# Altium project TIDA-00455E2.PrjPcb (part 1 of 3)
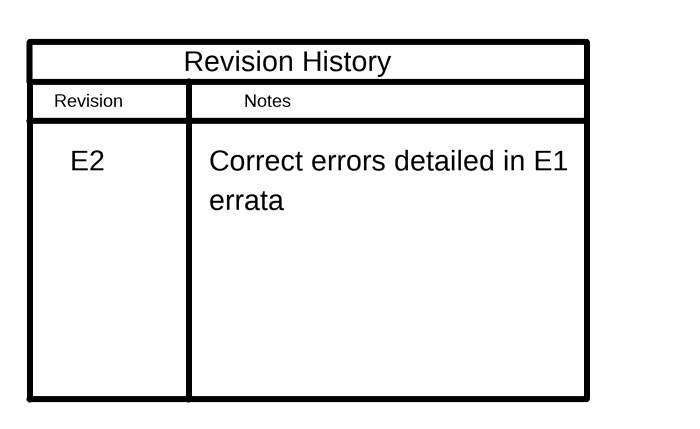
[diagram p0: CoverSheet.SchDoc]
TID: 00455; TechSupport: http://www.ti.com/support; SCH_Rev: E2.0; PRJ_Title: Four Channel Camera Board for TDA2x; PRJ_Number: TIDA-00455; PRJ_Engineer: Brian Shaffer; PRJ_Customer: Public Release; PCB_Rev: E2; EVM_Orderable: NO; CopyrightYear: 2015
10 sheets, 542 parts. Net scope: global (net labels, ports and power ports of the same name join across sheets).
Board file: TIDA-00455E2.PcbDoc
Sheets:
  CoverSheet.SchDoc
  cam_connections.SchDoc
  V_Batt_Supply.SchDoc
  Camera_Switch_and_Bucks.SchDoc
  Deserializer.SchDoc
  OV490_1.SchDoc
  OV490_2.SchDoc
  uC.SchDoc
  TDA2x_Conector.SchDoc
  Hardware.SchDoc

## Sheet CoverSheet.SchDoc: CoverSheet
size 431 x 279 mm; Date: Not shown in title block; ApprovedBy: Not shown in title block; CheckedBy: Not shown in title block; Author: Not shown in title block; CompanyName: Not shown in title block; DrawnBy: Brian Shaffer; Engineer: Not shown in title block; Organization: Not shown in title block; Address1: Not shown in title block; Address2: Not shown in title block; Address3: Not shown in title block; Address4: Not shown in title block; DocumentNumber: 1; Revision: Use project parameter SCH_Rev; SheetNumber: 1; SheetTotal: 10; PageSetup: Record=PageOptions¦CenterHorizontal=True¦CenterVertical=True¦PrintScale=1.00¦XCorrection=1.00¦YCorrection=1.00¦PrintKind=0¦BorderSize=5000000¦LeftOffset=0¦BottomOffset=0¦Orientation=2¦PaperLength=1000¦PaperWidth=1000¦Scale=100¦PaperSource=15¦PrintQuality=600¦MediaType=1¦DitherType=10¦PaperKind=Letter¦PrintScaleMode=1

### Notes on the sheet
- Revision
- Notes
- Revision History
- E2
- Correct errors detailed in E1
- errata

## Sheet cam_connections.SchDoc: cam_connections
size 431 x 279 mm; Date: Not shown in title block; ApprovedBy: Not shown in title block; CheckedBy: Not shown in title block; Author: Not shown in title block; CompanyName: Not shown in title block; DrawnBy: Brian Shaffer; Engineer: Not shown in title block; Organization: Not shown in title block; Address1: Not shown in title block; Address2: Not shown in title block; Address3: Not shown in title block; Address4: Not shown in title block; DocumentNumber: 2; Revision: Use project parameter SCH_Rev; SheetNumber: 2; SheetTotal: 10; PageSetup: Record=PageOptions¦CenterHorizontal=True¦CenterVertical=True¦PrintScale=0.64¦XCorrection=1.00¦YCorrection=1.00¦PrintKind=0¦BorderSize=5000000¦LeftOffset=0¦BottomOffset=0¦Orientation=2¦PaperLength=1000¦PaperWidth=1000¦Scale=100¦PaperSource=15¦PrintQuality=-3¦MediaType=1¦DitherType=10¦PrintScaleMode=1¦PaperKind=11x17¦PaperIndex=17
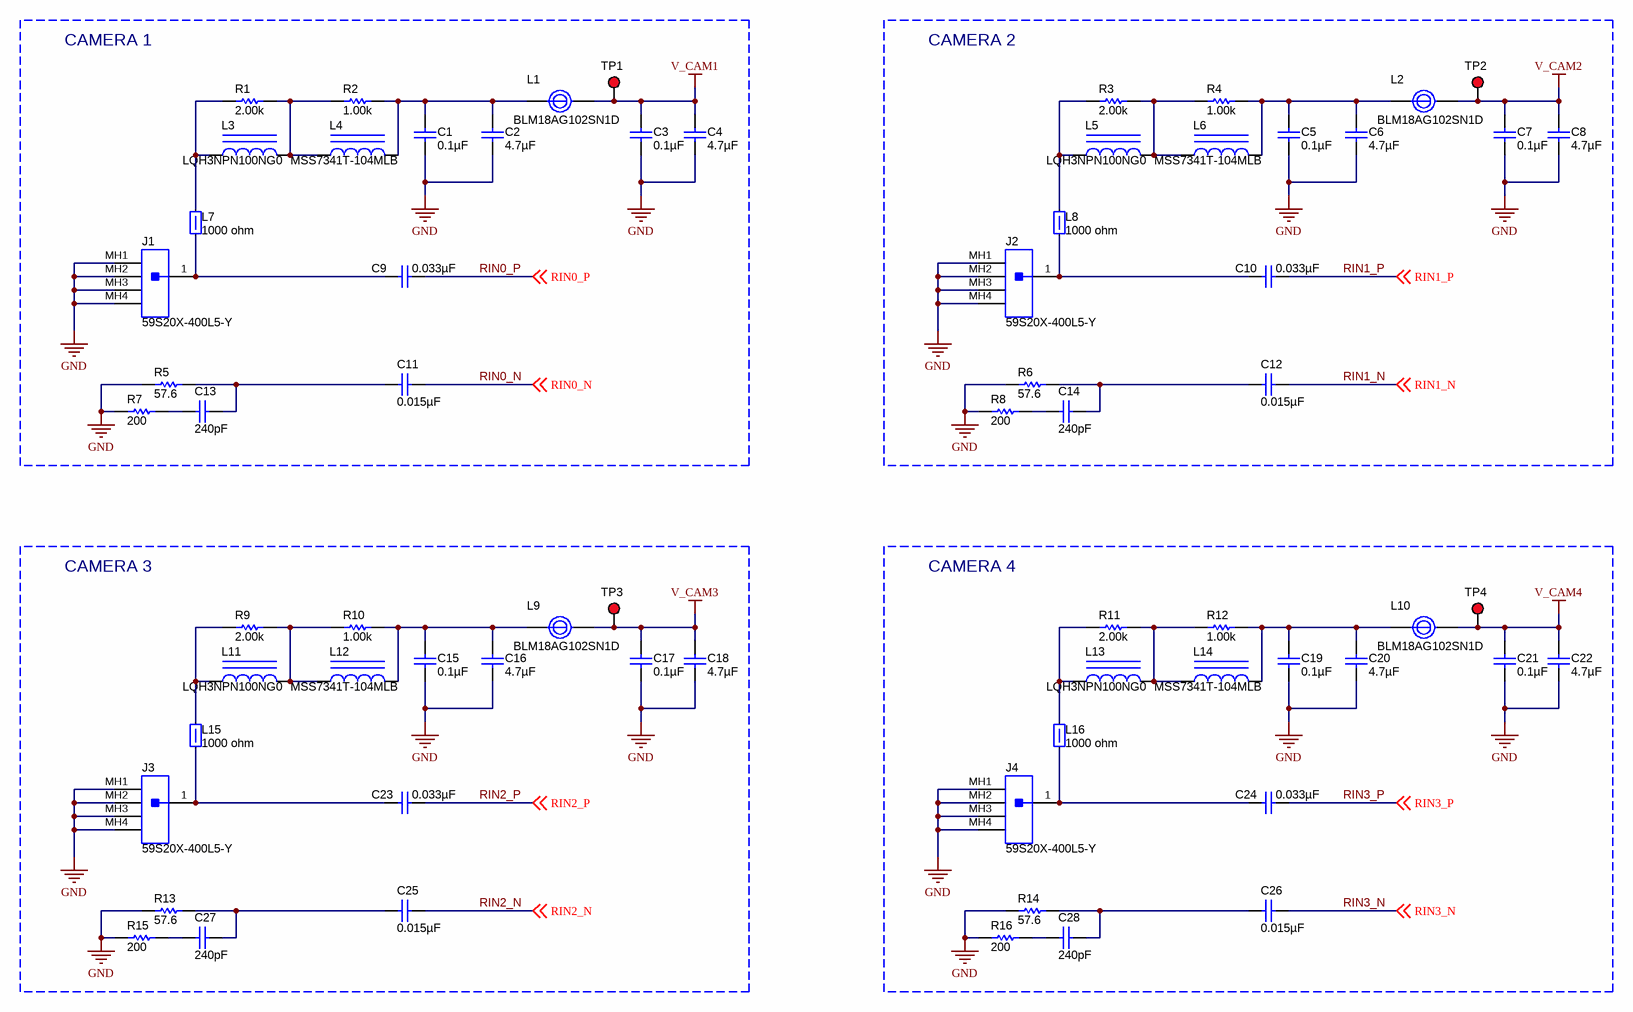
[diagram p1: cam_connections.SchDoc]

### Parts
C1  ValueDisplayed: 0.1µF  [0402]  (hidden comment: C1005X7R1H104K050BB)
C2  value 4.7µF  [0603L]  (hidden comment: GRM188R61E475KE11D)
C3  ValueDisplayed: 0.1µF  [0402]  (hidden comment: C1005X7R1H104K050BB)
C4  value 4.7µF  [0603L]  (hidden comment: GRM188R61E475KE11D)
C5  ValueDisplayed: 0.1µF  [0402]  (hidden comment: C1005X7R1H104K050BB)
C6  value 4.7µF  [0603L]  (hidden comment: GRM188R61E475KE11D)
C7  ValueDisplayed: 0.1µF  [0402]  (hidden comment: C1005X7R1H104K050BB)
C8  value 4.7µF  [0603L]  (hidden comment: GRM188R61E475KE11D)
C9  ValueDisplayed: 0.033µF  [0402]  (hidden comment: CGA2B3X7R1H333K050BB)
C10  ValueDisplayed: 0.033µF  [0402]  (hidden comment: CGA2B3X7R1H333K050BB)
C11  ValueDisplayed: 0.015µF  [0402]  (hidden comment: CGA2B3X7R1H153K050BB)
C12  ValueDisplayed: 0.015µF  [0402]  (hidden comment: CGA2B3X7R1H153K050BB)
C13  ValueDisplayed: 240pF  [0402]  (hidden comment: GRM1555C1H241JA01D)
C14  ValueDisplayed: 240pF  [0402]  (hidden comment: GRM1555C1H241JA01D)
C15  ValueDisplayed: 0.1µF  [0402]  (hidden comment: C1005X7R1H104K050BB)
C16  value 4.7µF  [0603L]  (hidden comment: GRM188R61E475KE11D)
C17  ValueDisplayed: 0.1µF  [0402]  (hidden comment: C1005X7R1H104K050BB)
C18  value 4.7µF  [0603L]  (hidden comment: GRM188R61E475KE11D)
C19  ValueDisplayed: 0.1µF  [0402]  (hidden comment: C1005X7R1H104K050BB)
C20  value 4.7µF  [0603L]  (hidden comment: GRM188R61E475KE11D)
C21  ValueDisplayed: 0.1µF  [0402]  (hidden comment: C1005X7R1H104K050BB)
C22  value 4.7µF  [0603L]  (hidden comment: GRM188R61E475KE11D)
C23  ValueDisplayed: 0.033µF  [0402]  (hidden comment: CGA2B3X7R1H333K050BB)
C24  ValueDisplayed: 0.033µF  [0402]  (hidden comment: CGA2B3X7R1H333K050BB)
C25  ValueDisplayed: 0.015µF  [0402]  (hidden comment: CGA2B3X7R1H153K050BB)
C26  ValueDisplayed: 0.015µF  [0402]  (hidden comment: CGA2B3X7R1H153K050BB)
C27  ValueDisplayed: 240pF  [0402]  (hidden comment: GRM1555C1H241JA01D)
C28  ValueDisplayed: 240pF  [0402]  (hidden comment: GRM1555C1H241JA01D)
J1  59S20X-400L5-Y  [Rosenberger_59S20X-400L5]
J2  59S20X-400L5-Y  [Rosenberger_59S20X-400L5]
J3  59S20X-400L5-Y  [Rosenberger_59S20X-400L5]
J4  59S20X-400L5-Y  [Rosenberger_59S20X-400L5]
L1  BLM18AG102SN1D  [0603L]
L2  BLM18AG102SN1D  [0603L]
L3  LQH3NPN100NG0  [LQH3NP_G0]
L4  MSS7341T-104MLB  [MSS7341]
L5  LQH3NPN100NG0  [LQH3NP_G0]
L6  MSS7341T-104MLB  [MSS7341]
L7  value 1000 ohm  [0402]  (hidden comment: BLM15HG102SN1D)
L8  value 1000 ohm  [0402]  (hidden comment: BLM15HG102SN1D)
L9  BLM18AG102SN1D  [0603L]
L10  BLM18AG102SN1D  [0603L]
L11  LQH3NPN100NG0  [LQH3NP_G0]
L12  MSS7341T-104MLB  [MSS7341]
L13  LQH3NPN100NG0  [LQH3NP_G0]
L14  MSS7341T-104MLB  [MSS7341]
L15  value 1000 ohm  [0402]  (hidden comment: BLM15HG102SN1D)
L16  value 1000 ohm  [0402]  (hidden comment: BLM15HG102SN1D)
R1  ValueDisplayed: 2.00k  [0603]  (hidden comment: CRCW06032K00FKEA)
R2  ValueDisplayed: 1.00k  [0603]  (hidden comment: ERJ-3EKF1001V)
R3  ValueDisplayed: 2.00k  [0603]  (hidden comment: CRCW06032K00FKEA)
R4  ValueDisplayed: 1.00k  [0603]  (hidden comment: ERJ-3EKF1001V)
R5  ValueDisplayed: 57.6  [0402]  (hidden comment: CRCW040257R6FKED)
R6  ValueDisplayed: 57.6  [0402]  (hidden comment: CRCW040257R6FKED)
R7  ValueDisplayed: 200  [0402]  (hidden comment: CRCW0402200RJNED)
R8  ValueDisplayed: 200  [0402]  (hidden comment: CRCW0402200RJNED)
R9  ValueDisplayed: 2.00k  [0603]  (hidden comment: CRCW06032K00FKEA)
R10  ValueDisplayed: 1.00k  [0603]  (hidden comment: ERJ-3EKF1001V)
R11  ValueDisplayed: 2.00k  [0603]  (hidden comment: CRCW06032K00FKEA)
R12  ValueDisplayed: 1.00k  [0603]  (hidden comment: ERJ-3EKF1001V)
R13  ValueDisplayed: 57.6  [0402]  (hidden comment: CRCW040257R6FKED)
R14  ValueDisplayed: 57.6  [0402]  (hidden comment: CRCW040257R6FKED)
R15  ValueDisplayed: 200  [0402]  (hidden comment: CRCW0402200RJNED)
R16  ValueDisplayed: 200  [0402]  (hidden comment: CRCW0402200RJNED)
TP1  5000  [Keystone5000]  (value not drawn)
TP2  5000  [Keystone5000]  (value not drawn)
TP3  5000  [Keystone5000]  (value not drawn)
TP4  5000  [Keystone5000]  (value not drawn)

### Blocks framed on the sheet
CAMERA 1: C1-C4 C9 C11 C13 J1 L1 L3 L4 L7 R1 R2 R5 R7 TP1
CAMERA 2: C5-C8 C10 C12 C14 J2 L2 L5 L6 L8 R3 R4 R6 R8 TP2
CAMERA 3: C15-C18 C23 C25 C27 J3 L9 L11 L12 L15 R9 R10 R13 R15 TP3
CAMERA 4: C19-C22 C24 C26 C28 J4 L10 L13 L14 L16 R11 R12 R14 R16 TP4

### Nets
GND: C1.2 C2.2 C3.2 C4.2 C5.2 C6.2 C7.2 C8.2 C15.2 C16.2 C17.2 C18.2 C19.2 C20.2 C21.2 C22.2 J1.MH1 J1.MH2 J1.MH3 J1.MH4 J2.MH1 J2.MH2 J2.MH3 J2.MH4 J3.MH1 J3.MH2 J3.MH3 J3.MH4 J4.MH1 J4.MH2 J4.MH3 J4.MH4 R5.1 R6.1 R7.1 R8.1 R13.1 R14.1 R15.1 R16.1
V_CAM1: C3.1 C4.1 L1.2 TP1.1
V_CAM2: C7.1 C8.1 L2.2 TP2.1
V_CAM3: C17.1 C18.1 L9.2 TP3.1
V_CAM4: C21.1 C22.1 L10.2 TP4.1
RIN0_N: C11.2 ; off-sheet RIN0_N
RIN0_P: C9.1 ; off-sheet RIN0_P
RIN1_N: C12.2 ; off-sheet RIN1_N
RIN1_P: C10.1 ; off-sheet RIN1_P
RIN2_N: C25.2 ; off-sheet RIN2_N
RIN2_P: C23.1 ; off-sheet RIN2_P
RIN3_N: C26.2 ; off-sheet RIN3_N
RIN3_P: C24.1 ; off-sheet RIN3_P
NetC1_1: C1.1 C2.1 L1.1 L4.2 R2.2
NetC5_1: C5.1 C6.1 L2.1 L6.2 R4.2
NetC9_2: C9.2 J1.1 L7.1
NetC10_2: C10.2 J2.1 L8.1
NetC11_1: C11.1 C13.2 R5.2
NetC12_1: C12.1 C14.2 R6.2
NetC13_1: C13.1 R7.2
NetC14_1: C14.1 R8.2
NetC15_1: C15.1 C16.1 L9.1 L12.2 R10.2
NetC19_1: C19.1 C20.1 L10.1 L14.2 R12.2
NetC23_2: C23.2 J3.1 L15.1
NetC24_2: C24.2 J4.1 L16.1
NetC25_1: C25.1 C27.2 R13.2
NetC26_1: C26.1 C28.2 R14.2
NetC27_1: C27.1 R15.2
NetC28_1: C28.1 R16.2
NetL3_1: L3.1 L7.2 R1.1
NetL3_2: L3.2 L4.1 R1.2 R2.1
NetL5_1: L5.1 L8.2 R3.1
NetL5_2: L5.2 L6.1 R3.2 R4.1
NetL11_1: L11.1 L15.2 R9.1
NetL11_2: L11.2 L12.1 R9.2 R10.1
NetL13_1: L13.1 L16.2 R11.1
NetL13_2: L13.2 L14.1 R11.2 R12.1

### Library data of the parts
C1 C3 C5 C7 C15 C17 C19 C21 = C1005X7R1H104K050BB: CAP, CERM, 0.1 µF, 50 V, +/- 10%, X7R, 0402; Manufacturer: TDK; Polarized: N; CompType: Capacitor; Value: 0.1uF; U/M: EA; Cap_F: 0.0000001; Tolerance_%: 10; Value1: Unknown; VDC_V: 50; Value2: 50V; TaMin_C: -55; TaMax_C: 125
C2 C4 C6 C8 C16 C18 C20 C22 = GRM188R61E475KE11D: CAP CER 4.7UF 25V 10% X5R 0603; Manufacturer: Murata Electronics North America
C9 C10 C23 C24 = CGA2B3X7R1H333K050BB: CAP, CERM, 0.033 µF, 50 V, +/- 10%, X7R, 0402; Manufacturer: TDK; Polarized: N; CompType: Capacitor; Value: 0.033uF; U/M: EA; Cap_F: 0.000000033; Tolerance_%: 10; Value1: Unknown; VDC_V: 50; Value2: 50V; TaMin_C: -55; TaMax_C: 125
C11 C12 C25 C26 = CGA2B3X7R1H153K050BB: CAP, CERM, 0.015 µF, 50 V, +/- 10%, X7R, 0402; Manufacturer: TDK; Polarized: N; CompType: Capacitor; Value: 0.015uF; U/M: EA; Cap_F: 0.000000015; Tolerance_%: 10; Value1: Unknown; VDC_V: 50; Value2: 50V; TaMin_C: -55; TaMax_C: 125
C13 C14 C27 C28 = GRM1555C1H241JA01D: CAP, CERM, 240 pF, 50 V, +/- 5%, C0G/NP0, 0402; Manufacturer: MuRata; Polarized: N; CompType: Capacitor; Value: 240pF; U/M: EA; Cap_F: 0.00000000024; Tolerance_%: 5; Value1: Unknown; VDC_V: 50; Value2: 50V; TaMin_C: -55; TaMax_C: 125
J1-J4 = 59S20X-400L5-Y: RIGHT ANGLE PLUG FOR PCB; Manufacturer: Rosenberger; SymbolCreator: x0208325; U/M: EA
L1 L2 L9 L10 = BLM18AG102SN1D: FERRITE CHIP 1000 OHM 400MA 0603; Manufacturer: Murata Electronics North America; Impedance @ Frequency: 1 kOhm @ 100MHz; DCR_Ohm: 500 mOhm Max; Filter Type: Differential Mode - Single
L3 L5 L11 L13 = LQH3NPN100NG0: Inductor, Wirewound, Ferrite, 10 µH, 0.5 A, 0.57 ohm, SMD; Manufacturer: MuRata; Value: 10uH; Ind_H: 10.0E-6; ValueDisplayed: 10µH; Imax_A: 0.5; Irms: 0.63A @ 40C rise; Isat: 0.5A @ 30% inductance drop; DCR_ohm: 0.57; Value2: 0.5A
L4 L6 L12 L14 = MSS7341T-104MLB: Inductor, Shielded Drum Core, Ferrite, 100 µH, 0.7 A, 0.28 ohm, SMD; Manufacturer: Coilcraft; Value: 100uH; Ind_H: 100.0E-6; ValueDisplayed: 100µH; Imax_A: 0.7; Irms: 1.15A @ 40C rise; Isat: 0.7A @ 30% inductance drop; DCR_ohm: 0.28; Value2: 0.7A
L7 L8 L15 L16 = BLM15HG102SN1D: Ferrite Bead, 1000 ohm @ 100 MHz, 0.25 A, 0402; Manufacturer: MuRata; Imax_A: 0.25; DCR_ohm: 1.1; Value1: 1.1 ohm; Value2: 0.25A; ZTyp@100MHz_Ohm: 1000
R1 R3 R9 R11 = CRCW06032K00FKEA: RES, 2.00 k, 1%, 0.1 W, 0603; Manufacturer: Vishay-Dale; CompType: Resistor; Value: 2.00k; Res_ohm: 2000; Value_Code: 2k00; Tolerance_%: 1; Power_W: 0.1; Value2: 0.1W; VDC_V: 75; TempCo: 100 ppm/C; EIA_Code: E96; U/M: EA
R2 R4 R10 R12 = ERJ-3EKF1001V: RES, 1.00 k, 1%, 0.1 W, 0603; Manufacturer: Panasonic; CompType: Resistor; Value: 1.00k; Res_ohm: 1000; Value_Code: 1k00; Tolerance_%: 1; Power_W: 0.1; Value2: 0.1W; VDC_V: 75; TempCo: 100 ppm/C; EIA_Code: E96; U/M: EA
R5 R6 R13 R14 = CRCW040257R6FKED: RES, 57.6, 1%, 0.063 W, 0402; Manufacturer: Vishay-Dale; CompType: Resistor; Value: 57.6; Value_Code: 57R6; Tolerance_%: 1; Power_W: 0.063; Value2: 0.063W; VDC_V: 50; TempCo: 100 ppm/C; EIA_Code: E96; U/M: EA
R7 R8 R15 R16 = CRCW0402200RJNED: RES, 200, 5%, 0.063 W, 0402; Manufacturer: Vishay-Dale; CompType: Resistor; Value: 200; Value_Code: 200R; Tolerance_%: 5; Power_W: 0.063; Value2: 0.063W; VDC_V: 50; TempCo: 200 ppm/C; EIA_Code: E24; U/M: EA
TP1-TP4 = 5000: Test Point, Miniature, Red, TH; Manufacturer: Keystone; CompType: Test Point Loop; U/M: EA

## Sheet V_Batt_Supply.SchDoc: V_Batt_Supply
size 431 x 279 mm; Date: Not shown in title block; ApprovedBy: Not shown in title block; CheckedBy: Not shown in title block; Author: Not shown in title block; CompanyName: Not shown in title block; DrawnBy: Brian Shaffer; Engineer: Not shown in title block; Organization: Not shown in title block; Address1: Not shown in title block; Address2: Not shown in title block; Address3: Not shown in title block; Address4: Not shown in title block; DocumentNumber: 3; Revision: Use project parameter SCH_Rev; SheetNumber: 3; SheetTotal: 10; PageSetup: Record=PageOptions¦CenterHorizontal=True¦CenterVertical=True¦PrintScale=0.62¦XCorrection=1.00¦YCorrection=1.00¦PrintKind=0¦BorderSize=5000000¦LeftOffset=0¦BottomOffset=0¦Orientation=2¦PaperLength=1000¦PaperWidth=1000¦Scale=100¦PaperSource=15¦PrintQuality=600¦MediaType=1¦DitherType=10¦PrintScaleMode=1¦PaperKind=Letter
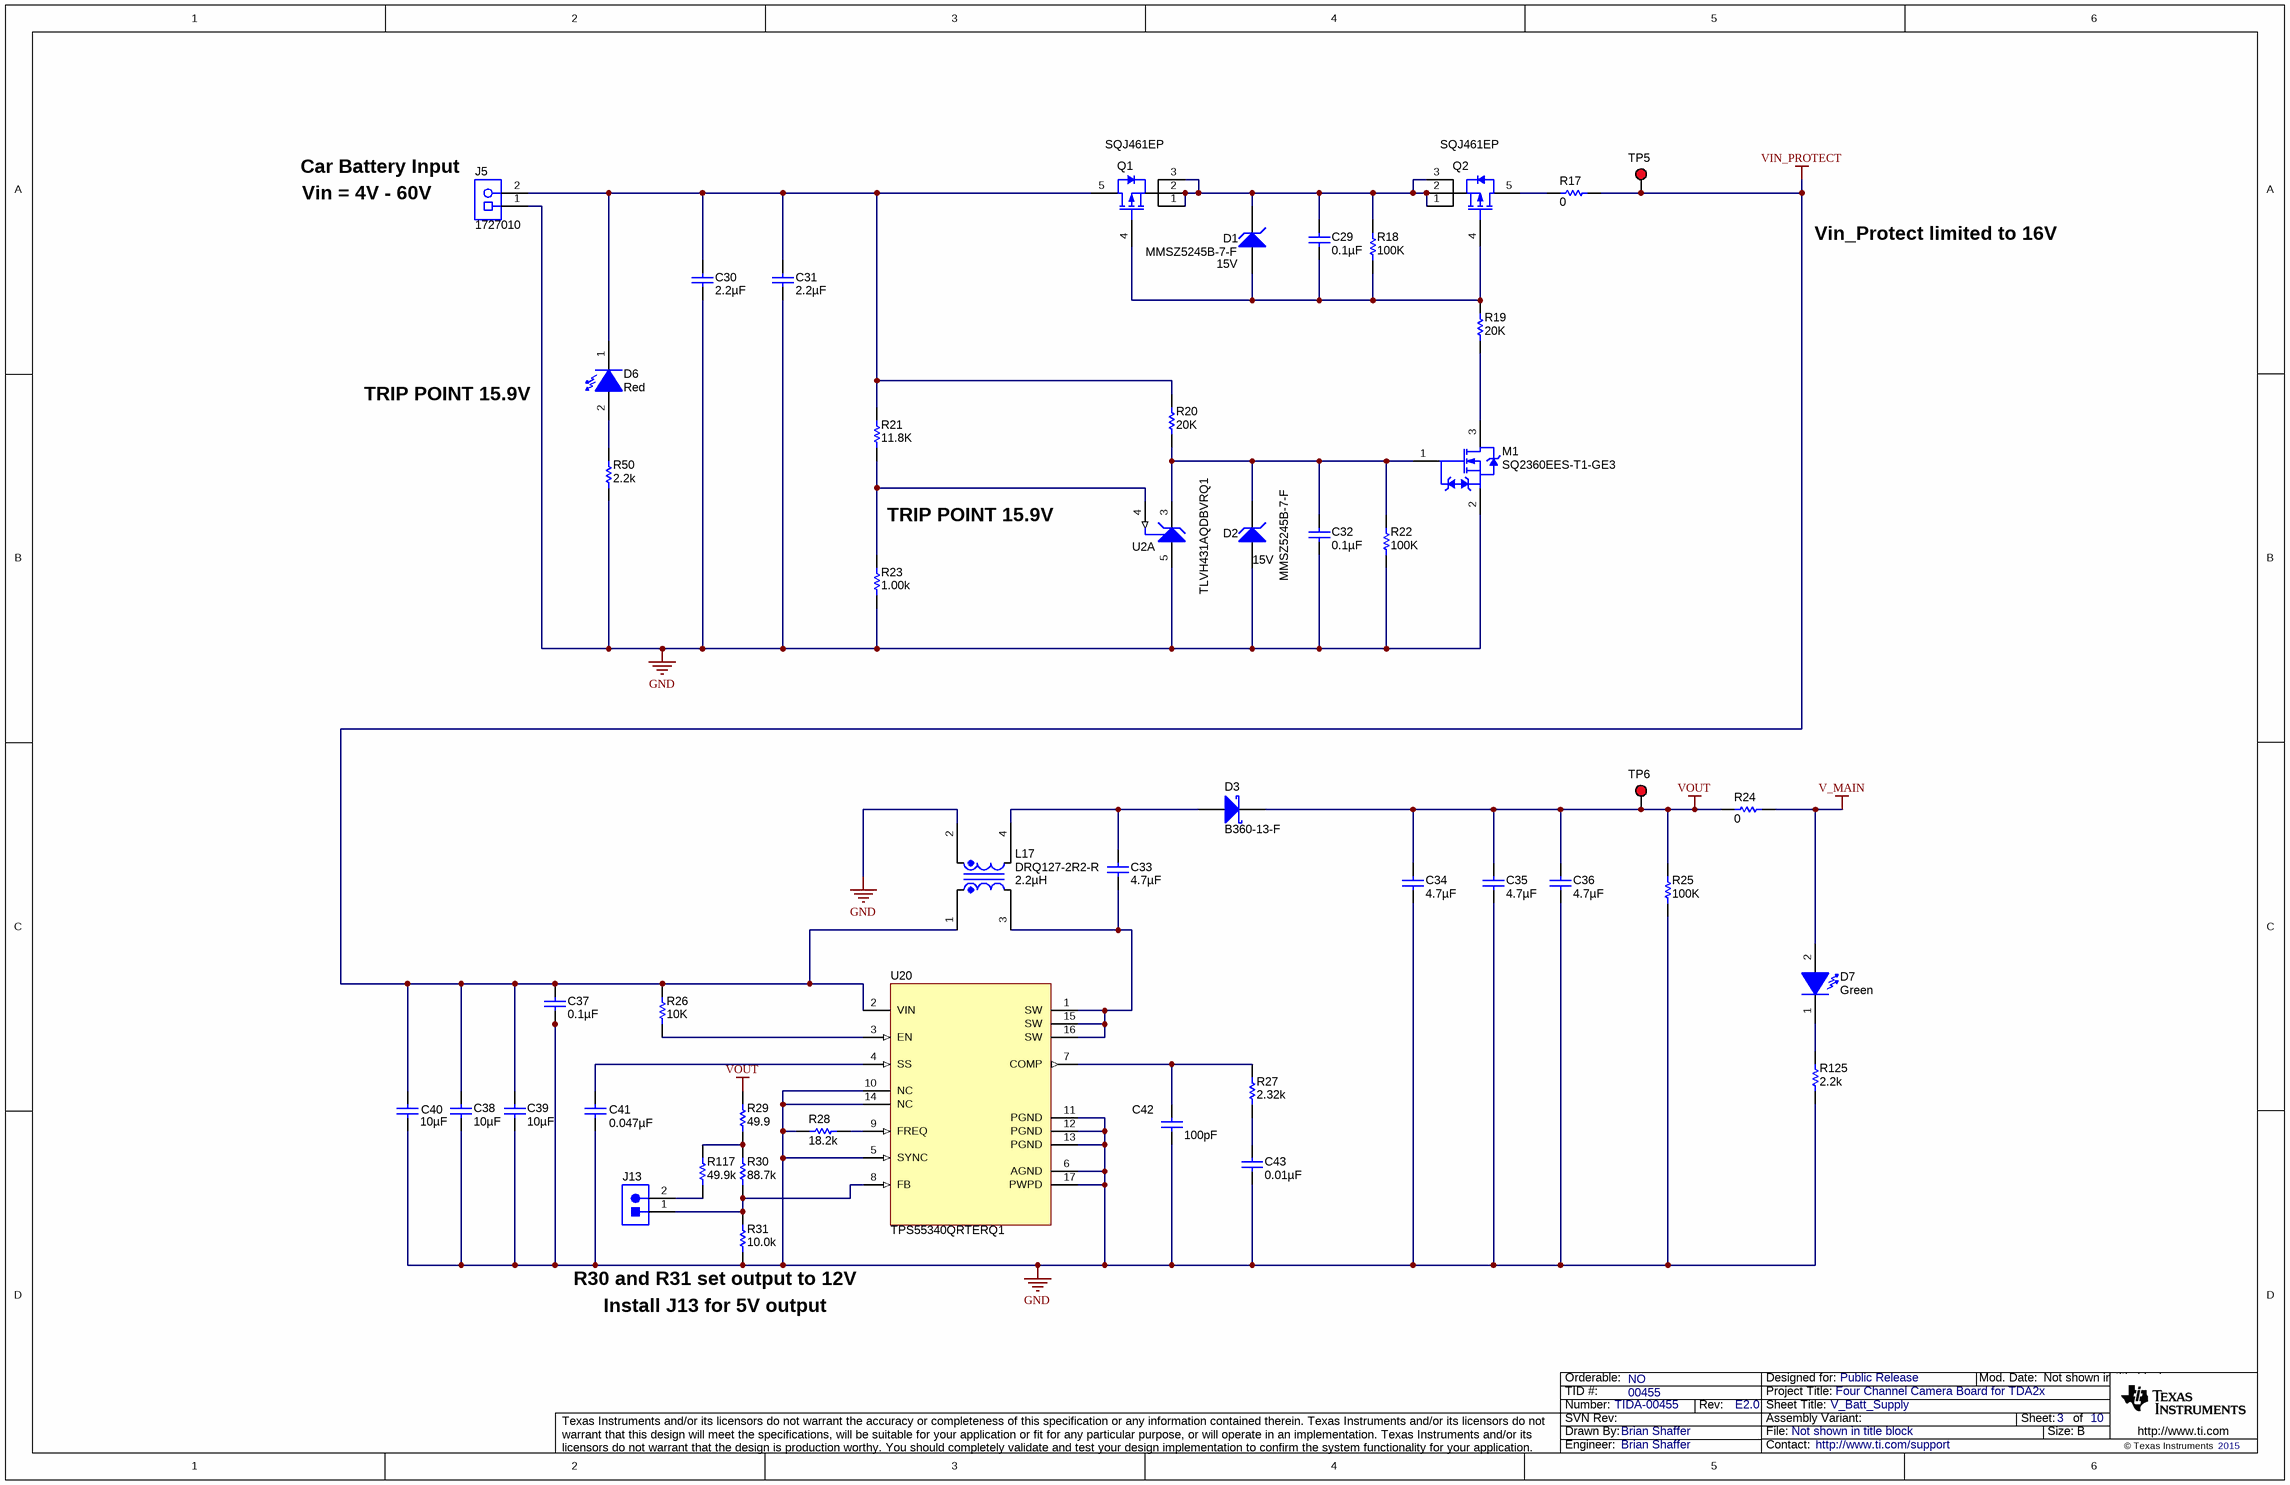
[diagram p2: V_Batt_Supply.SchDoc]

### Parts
C29  ValueDisplayed: 0.1µF  [0603]  (hidden comment: C1608X7R1H104K)
C30  ValueDisplayed: 2.2µF  [1210]  (hidden comment: GRM32ER72A225KA35L)
C31  ValueDisplayed: 2.2µF  [1210]  (hidden comment: GRM32ER72A225KA35L)
C32  ValueDisplayed: 0.1µF  [0603]  (hidden comment: C1608X7R1H104K)
C33  ValueDisplayed: 4.7µF  [1206]  (hidden comment: C3216X7R1E475M)
C34  ValueDisplayed: 4.7µF  [1206]  (hidden comment: C3216X7R1E475M)
C35  ValueDisplayed: 4.7µF  [1206]  (hidden comment: C3216X7R1E475M)
C36  ValueDisplayed: 4.7µF  [1206]  (hidden comment: C3216X7R1E475M)
C37  ValueDisplayed: 0.1µF  [0402]  (hidden comment: GRM155R70J104KA01D)
C38  ValueDisplayed: 10µF  [1206]  (hidden comment: GRM31CR71E106KA12L)
C39  ValueDisplayed: 10µF  [1206]  (hidden comment: GRM31CR71E106KA12L)
C40  ValueDisplayed: 10µF  [1206]  (hidden comment: GRM31CR71E106KA12L)
C41  ValueDisplayed: 0.047µF  [0402]  (hidden comment: GRM155R70J473KA01D)
C42  ValueDisplayed: 100pF  [0402]  (hidden comment: CC0402KRX7R9BB101)
C43  ValueDisplayed: 0.01µF  [0402]  (hidden comment: GRM155R71C103KA01D)
D1  MMSZ5245B-7-F  value 15V  [SOD-123]
D2  MMSZ5245B-7-F  value 15V  [SOD-123]
D3  B360-13-F  [SMC]
D6  value Red  [SML-P1_RED]  (hidden comment: SML-P12UTT86)
D7  value Green  [SML-P1_GREEN]  (hidden comment: SML-P12PTT86)
J5  1727010  [PhoenixConact_1727010]
J13  PEC02SAAN  [CONN_PEC02SAAN]  (value not drawn)
L17  DRQ127-2R2-R  ValueDisplayed: 2.2µH  [DRQ127]
M1  SQ2360EES-T1-GE3  [SOT-23]
Q1  SQJ461EP  [PowerPAK_SO-8L]
Q2  SQJ461EP  [PowerPAK_SO-8L]
R17  ValueDisplayed: 0  [2010]  (hidden comment: CRCW20100000Z0EF)
R18  value 100K  [0603]  (hidden comment: ERJ-3EKF1003V)
R19  value 20K  [0603]  (hidden comment: RC0603FR-0720KL)
R20  value 20K  [0603]  (hidden comment: RC0603FR-0720KL)
R21  value 11.8K  [0603]  (hidden comment: CRCW060311K8FK)
R22  value 100K  [0603]  (hidden comment: ERJ-3EKF1003V)
R23  value 1.00k  [0603]  (hidden comment: CRCW06031K00FKEA)
R24  value 0  [0805_HV]  (hidden comment: CRCW08050000Z0EA)
R25  value 100K  [1206]  (hidden comment: CRCW1206100KJNEA)
R26  value 10K  [0402]  (hidden comment: CRCW040210K0JNED)
R27  value 2.32k  [0402]  (hidden comment: CRCW04022K32FKED)
R28  value 18.2k  [0402]  (hidden comment: CRCW040218K2FKED)
R29  value 49.9  [0402]  (hidden comment: CRCW040249R9FKED)
R30  ValueDisplayed: 88.7k  [0402]  (hidden comment: CRCW040288K7FKED)
R31  value 10.0k  [0402]  (hidden comment: CRCW040210K0FKED)
R50  ValueDisplayed: 2.2k  [0402]  (hidden comment: CRCW04022K20JNED)
R117  ValueDisplayed: 49.9k  [0402]  (hidden comment: CRCW040249K9FKED)
R125  ValueDisplayed: 2.2k  [0402]  (hidden comment: CRCW04022K20JNED)
TP5  5000  [Keystone5000]  (value not drawn)
TP6  5000  [Keystone5000]  (value not drawn)
U2  TLVH431AQDBVRQ1  [DBV0005A_N]  (part A of 2)
U20  TPS55340QRTERQ1  [RTE0016C]

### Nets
GND: C30.1 C31.1 C32.2 C34.2 C35.2 C36.2 C37.2 C38.2 C39.2 C40.2 C41.2 C42.2 C43.2 D2.2(A) J5.1 L17.2 M1.2(S) R22.2 R23.1 R25.1 R28.1 R31.2 R50.1 R125.1 U2.5(ANODE) U20.5(SYNC) U20.6(AGND) U20.10(NC) U20.11(PGND) U20.12(PGND) U20.13(PGND) U20.14(NC) U20.17(PWPD)
V_MAIN: D7.2(A) R24.2
VIN_PROTECT: C37.1 C38.1 C39.1 C40.1 L17.1 R17.2 R26.1 TP5.1 U20.2(VIN)
VOUT: C34.1 C35.1 C36.1 D3.1(K) R24.1 R25.2 R29.1 TP6.1
NetC29_1: C29.1 D1.1(K) Q1.1(S) Q1.2(S) Q1.3(S) Q2.1(S) Q2.2(S) Q2.3(S) R18.1
NetC29_2: C29.2 D1.2(A) Q1.4(G) Q2.4(G) R18.2 R19.2
NetC30_2: C30.2 C31.2 D6.1(K) J5.2 Q1.5(D) R20.2 R21.2
NetC32_1: C32.1 D2.1(K) M1.1(G) R20.1 R22.1 U2.3(CATHODE)
NetC33_1: C33.1 D3.2(A) L17.4
NetC33_2: C33.2 L17.3 U20.1(SW) U20.15(SW) U20.16(SW)
NetC41_1: C41.1 U20.4(SS)
NetC42_1: C42.1 R27.2 U20.7(COMP)
NetC43_1: C43.1 R27.1
NetD6_2: D6.2(A) R50.2
NetD7_1: D7.1(K) R125.2
NetJ13_1: J13.1 R30.1 R31.1 U20.8(FB)
NetJ13_2: J13.2 R117.1
NetM1_3: M1.3(D) R19.1
NetQ2_5: Q2.5(D) R17.1
NetR21_1: R21.1 R23.2 U2.4(REF)
NetR26_2: R26.2 U20.3(EN)
NetR28_2: R28.2 U20.9(FREQ)
NetR29_2: R29.2 R30.2 R117.2

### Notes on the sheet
- (near J5) Car Battery Input
- Vin = 4V - 60V
- Vin_Protect limited to 16V
- TRIP POINT 15.9V
- (near R31) R30 and R31 set output to 12V
- (near R31) Install J13 for 5V output

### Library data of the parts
C29 C32 = C1608X7R1H104K: CAP, CERM, 0.1uF, 50V, +10/%, X7R, 0603; Manufacturer: TDK; Polarized: N; CompType: Capacitor; U/M: EA; Cap_F: 0.0000001; Tolerance_%: 10; ESR_Ohm: 0.017; Value1: 0.017 ohm; VDC_V: 50; TaMin_C: -55; TaMax_C: 125; EN: 102-1-01819
C30 C31 = GRM32ER72A225KA35L: Cap, Cer-X7R, 2.2uF, 100V, 10%, 1210; Manufacturer: MuRata; PART Name: SCH_LIB\CAP_NP; Polarized: N; CompType: Capacitor; U/M: EA; Cap_F: 0.0000022; Tolerance_%: 10; ESR_Ohm: 0.007; Value1: 0.007 ohm; VDC_V: 100; TempCo: X7R; IRMS_A: 4.4; TaMin_C: -55; TaMax_C: 125; EN: 102-1-00662; Mfg: MURATA MANUFACTURING CO,LTD; Onhand: 1720
C33-C36 = C3216X7R1E475M: CAP, CERM, 4.7uF, 25V, +/-20%, X7R, 1206; Manufacturer: TDK; Polarized: N; CompType: Capacitor; U/M: EA; Cap_F: 0.0000047; Tolerance_%: 20; ESR_Ohm: 0.0063; Value1: 0.0063 ohm; VDC_V: 25; TaMin_C: -55; TaMax_C: 125; EN: 102-1-01891
C37 = GRM155R70J104KA01D: Cap, Cer-X7R, 0.1uF, 6.3V, 10%, 0402; Manufacturer: MuRata; Polarized: N; CompType: Capacitor; U/M: EA; Cap_F: 0.0000001; Tolerance_%: 10; Value1: Unknown; VDC_V: 6.3; TempCo: X7R; TaMin_C: -55; TaMax_C: 125; EN: 102-1-01892; Mfg: MURATA MANUFACTURING CO,LTD; Onhand: 0
C38-C40 = GRM31CR71E106KA12L: Cap, Cer-X7R, 10uF, 25V, 10%, 1206; Manufacturer: MuRata; Polarized: N; CompType: Capacitor; U/M: EA; Cap_F: 0.00001; Tolerance_%: 10; Value1: Unknown; VDC_V: 25; TempCo: X7R; TaMin_C: -55; TaMax_C: 125; Cap_Case: 2220; EN: 102-1-01893; Mfg: MURATA MANUFACTURING CO,LTD; Onhand: 0
C41 = GRM155R70J473KA01D: Cap, Cer-X7R, 0.047uF, 6.3V, 10%, 0402; Manufacturer: MuRata; Polarized: N; CompType: Capacitor; U/M: EA; Cap_F: 0.000000047; Tolerance_%: 10; Value1: Unknown; VDC_V: 6.3; TempCo: X7R; TaMin_C: -55; TaMax_C: 125; EN: 102-1-01894; Mfg: MURATA MANUFACTURING CO,LTD; Onhand: 0
C42 = CC0402KRX7R9BB101: Cap, Cer-X7R, 100pF, 50V, 10%, 0402; Manufacturer: Yageo America; PART Name: SCH_LIB\CAP_NP; Polarized: N; CompType: Capacitor; U/M: EA; Cap_F: 0.0000000001; Tolerance_%: 10; Value1: Unknown; VDC_V: 50; TempCo: X7R; TaMin_C: -55; TaMax_C: 125; DECAL Name: 0402,0402_HD; EN: 102-1-00053; Mfg: YAGEO; Onhand: 16933
C43 = GRM155R71C103KA01D: Cap, Cer-X7R, 10000pF, 16V, 10%, 0402; Manufacturer: MuRata; Polarized: N; CompType: Capacitor; U/M: EA; Cap_F: 0.00000001; Tolerance_%: 10; Value1: Unknown; VDC_V: 16; TempCo: X7R; TaMin_C: -55; TaMax_C: 125; EN: 102-1-01895; Mfg: MURATA MANUFACTURING CO,LTD; Onhand: 0
D1 D2 = MMSZ5245B-7-F: Diode, Zener, 15 V, 500 mW, SOD-123; Manufacturer: Diodes Inc.; SymbolCreator: a0412235; U/M: EA; Power_W: 0.5; Vz_V: 15; Value1: 0.5W; RJA_CperW: 350
D3 = B360-13-F: Diode, Schottky, 3A, 60V, SMC; Manufacturer: Diodes Inc.; U/M: EA; Vf_V: 0.7; Value2: 0.7V; Io_A: 3; Vr_V: 60; TJmax_C: 125; RJC_CperW: 20; DECAL Name: DIO-SMC_CASE_403; EN: 106-2-00038; Mfg: DIODES INCORPORATED; Onhand: 10
D6 = SML-P12UTT86: LED, Red, SMD; Manufacturer: Rohm; Type: AlInGaP; Vf_V: 2; Value2: 2V; Io_A: 0.02; Value1: W; U/M: EA
D7 = SML-P12PTT86: LED, Green, SMD; Manufacturer: Rohm; Type: AlInGaP; Vf_V: 2.2; Value2: 2.2V; Io_A: 0.02; Value1: W; U/M: EA
J5 = 1727010: Conn Term Block, 2POS, 3.81mm, TH; Manufacturer: Phoenix Contact; SymbolCreator: a0412235; CompType: Terminal Block; U/M: EA; Value: 2x1
J13 = PEC02SAAN: Header, 100mil, 2x1, Tin, TH; Manufacturer: Sullins Connector Solutions; SymbolCreator: a0412235; U/M: EA
L17 = DRQ127-2R2-R: Ind, Dual, 2.2uH, 20%, 6.23A, 8.05mE, Shielded, SMD; Manufacturer: Coiltronics; SymbolCreator: a0412235; Ind_H: 2.2E-6; CompType: Coupled Inductor; DCR_ohm: 3.73; Isat: 25.5; Tolerance_%: 20; EN: 103-1-00256; Onhand: 0
M1 = SQ2360EES-T1-GE3: MOSFET, N/P-CH, 60 V, 4.4 A, SOT-23; Manufacturer: Vishay-Siliconix; Alternate Manufacturer: None; SymbolCreator: x0208325; U/M: EA; ChType: N; Value: 60V; VdsMax_V: 60; Value1: 0.13 ohm; Rdson45_ohm: 0.13; Value2: 7.4 nC; QgTyp_nC: 7.4; Vgs_V: 20; IdsMax_A: 4.4
Q1 Q2 = SQJ461EP: MOSFET, P-CH, -60V, 30A, PowerPAK_SO-8L; Manufacturer: Vishay-Siliconix; Alternate Manufacturer: None; SymbolCreator: a0411947; U/M: EA; ChType: P; VdsMax_V: -60; Value1: 0.031 ohm; Rdson45_Ohm: 0.031; Value2: 90 nC; QgTyp_nC: 90; Vgs_V: 20; IdsMax_A: 30; EN: 107-2-00088
R17 = CRCW20100000Z0EF: RES, 0, 5%, 0.75 W, 2010; Manufacturer: Vishay-Dale; CompType: Resistor; Value: 0; Value_Code: 0000; Tolerance_%: 5; Power_W: 0.75; Value2: 0.75W; TempCo: ppm/C; EIA_Code: E24; U/M: EA
R18 R22 = Resistor: Res, Chip, 100K, 1/10W, 1%, 0603; Manufacturer: Panasonic Electronic Components; PART Name: SCH_LIB\RES; U/M: EA; Power_W: 0.1W, 1/10W; TempCo: ±100ppm/°C; EN: 101-1-01158; Mfg: PANASONIC; Onhand: 3656
R19 R20 = RC0603FR-0720KL: Res, Chip, 20K, 1/10W, 1%, 0603; Manufacturer: Yageo America; PART Name: SCH_LIB\RES; CompType: Resistor; Res_ohm: 20000; Value_Code: 20k0; Tolerance_%: 1; Power_W: 0.1; Value2: 0.1W; VDC_V: 150; TempCo: 200 ppm/C; EIA_Code: E96; U/M: EA; EN: 101-1-01091; Mfg: YAGEO; Onhand: 9649
R21 = CRCW060311R8FKEA: RES, 11.8 ohm, 1%, 0.1W, 0603; Manufacturer: Vishay-Dale; CompType: Resistor; Res_ohm: 11800; Value_Code: 11R8; Tolerance_%: 1; Power_W: 0.1; VDC_V: 75; TempCo: 100 ppm/C; EIA_Code: E96; U/M: EA; EN: 101-1-01069
R23 = CRCW06031K00FKEA: RES, 1.00k ohm, 1%, 0.1W, 0603; Manufacturer: Vishay-Dale; CompType: Resistor; Res_ohm: 1000; Value_Code: 1k00; Tolerance_%: 1; Power_W: 0.1; VDC_V: 75; TempCo: 100 ppm/C; EIA_Code: E96; U/M: EA; EN: 101-1-00966
R24 = CRCW08050000Z0EA: Res, Chip, 0E, 1/8W, JUMP, 0805; Manufacturer: Vishay-Dale; CompType: Resistor; Value_Code: 0000; Tolerance_%: 5; Value1: 5%; Power_W: 0.125; Value2: 0.125W; VDC_V: 150; TempCo: 200 ppm/C; EIA_Code: E24; U/M: EA; EN: 101-1-03582; Mfg: VISHAY
R25 = CRCW1206100KJNEA: Res, Chip, 100K, 1/4W, 5%, 1206; Manufacturer: Vishay-Dale; PART Name: SCH_LIB\RES; CompType: Resistor; Res_ohm: 100000; Tolerance_%: 5; Power_W: 0.25; Value2: 0.25W; VDC_V: 200; TempCo: 200 ppm/C; EIA_Code: E24; U/M: EA; EN: 101-1-03324; Mfg: VISHAY; Onhand: 0
R26 = CRCW040210K0JNED: Res, Chip, 10K, 1/16W, 5%, 0402; Manufacturer: Vishay-Dale; PART Name: SCH_LIB\RES; CompType: Resistor; Res_ohm: 10000; Value_Code: 10k0; Tolerance_%: 5; Power_W: 0.063; Value2: 0.063W; VDC_V: 50; TempCo: 200 ppm/C; EIA_Code: E24; U/M: EA; EN: 101-1-02793; Mfg: VISHAY; Onhand: 7938
R27 = CRCW04022K32FKED: RES, 2.32k ohm, 1%, 0.063W, 0402; Manufacturer: Vishay-Dale; CompType: Resistor; Res_ohm: 2320; Value_Code: 2k32; Tolerance_%: 1; Power_W: 0.063; VDC_V: 50; TempCo: 100 ppm/C; EIA_Code: E96; U/M: EA; EN: 101-1-00328
R28 = CRCW040218K2FKED: RES, 18.2k ohm, 1%, 0.063W, 0402; Manufacturer: Vishay-Dale; CompType: Resistor; Res_ohm: 18200; Value_Code: 18k2; Tolerance_%: 1; Power_W: 0.063; VDC_V: 50; TempCo: 100 ppm/C; EIA_Code: E96; U/M: EA; EN: 101-1-00414
R29 = CRCW040249R9FKED: RES, 49.9 ohm, 1%, 0.063W, 0402; Manufacturer: Vishay-Dale; CompType: Resistor; Value_Code: 49R9; Tolerance_%: 1; Power_W: 0.063; VDC_V: 50; TempCo: 100 ppm/C; EIA_Code: E96; U/M: EA; EN: 101-1-00168
R30 = CRCW040288K7FKED: RES, 88.7 k, 1%, 0.063 W, 0402; Manufacturer: Vishay-Dale; CompType: Resistor; Value: 88.7k; Res_ohm: 88700; Value_Code: 88k7; Tolerance_%: 1; Power_W: 0.063; Value2: 0.063W; VDC_V: 50; TempCo: 100 ppm/C; EIA_Code: E96; U/M: EA
R31 = CRCW040210K0FKED: RES, 10.0k ohm, 1%, 0.063W, 0402; Manufacturer: Vishay-Dale; CompType: Resistor; Res_ohm: 10000; Value_Code: 10k0; Tolerance_%: 1; Power_W: 0.063; VDC_V: 50; TempCo: 100 ppm/C; EIA_Code: E96; U/M: EA; EN: 101-1-00389
R50 R125 = CRCW04022K20JNED: RES, 2.2 k, 5%, 0.063 W, 0402; Manufacturer: Vishay-Dale; CompType: Resistor; Value: 2.2k; Res_ohm: 2200; Value_Code: 2k20; Tolerance_%: 5; Power_W: 0.063; Value2: 0.063W; VDC_V: 50; TempCo: 200 ppm/C; EIA_Code: E24; U/M: EA
R117 = CRCW040249K9FKED: RES, 49.9 k, 1%, 0.063 W, 0402; Manufacturer: Vishay-Dale; CompType: Resistor; Value: 49.9k; Res_ohm: 49900; Value_Code: 49k9; Tolerance_%: 1; Power_W: 0.063; Value2: 0.063W; VDC_V: 50; TempCo: 100 ppm/C; EIA_Code: E96; U/M: EA
TP5 TP6 = 5000: as TP1 on sheet cam_connections
U2 = TLVH431AQDBVRQ1: Automotive Catalog Low-Voltage Adjustable Precision Shunt Regulator, 80 mA, -40 to 125 degC, 5-pin SOT-23 (DBV), Green (RoHS & no Sb/Br); Manufacturer: Texas Instruments; Alternate Manufacturer: None; Alternate PartNumber: Equivalent; PartNumber: TLVH431AQDBVRQ1A; Initial Accuracy @ 25/deg C(%): 1; Iout/Iz(Max)(mA): 80; SubFamily: Shunt Voltage Reference; Temp Coeff(Max)(ppm/ degree C): 129; VO Adj(Max)(V): 18; VO Adj(Min)(V): 1.24
U20 = TPS55340QRTERQ1: Integrated 5-A 40-V Wide Input Range Boost/SEPIC/Flyback DC-DC Regulator, RTE0016C; Alternate PartNumber: TPS55340QRTETQ1; Manufacturer: Texas Instruments; SymbolCreator: x0208326; CompType: IC; U/M: EA

## Sheet Camera_Switch_and_Bucks.SchDoc: Camera_Switch_and_Bucks
size 431 x 279 mm; Date: Not shown in title block; ApprovedBy: Not shown in title block; CheckedBy: Not shown in title block; Author: Not shown in title block; CompanyName: Not shown in title block; DrawnBy: Brian Shaffer; Engineer: Not shown in title block; Organization: Not shown in title block; Address1: Not shown in title block; Address2: Not shown in title block; Address3: Not shown in title block; Address4: Not shown in title block; DocumentNumber: 4; Revision: Use project parameter SCH_Rev; SheetNumber: 4; SheetTotal: 10; PageSetup: Record=PageOptions¦CenterHorizontal=True¦CenterVertical=True¦PrintScale=0.64¦XCorrection=1.00¦YCorrection=1.00¦PrintKind=0¦BorderSize=5000000¦LeftOffset=0¦BottomOffset=0¦Orientation=2¦PaperLength=1000¦PaperWidth=1000¦Scale=100¦PaperSource=15¦PrintQuality=600¦MediaType=1¦DitherType=10¦PrintScaleMode=1¦PaperKind=Letter
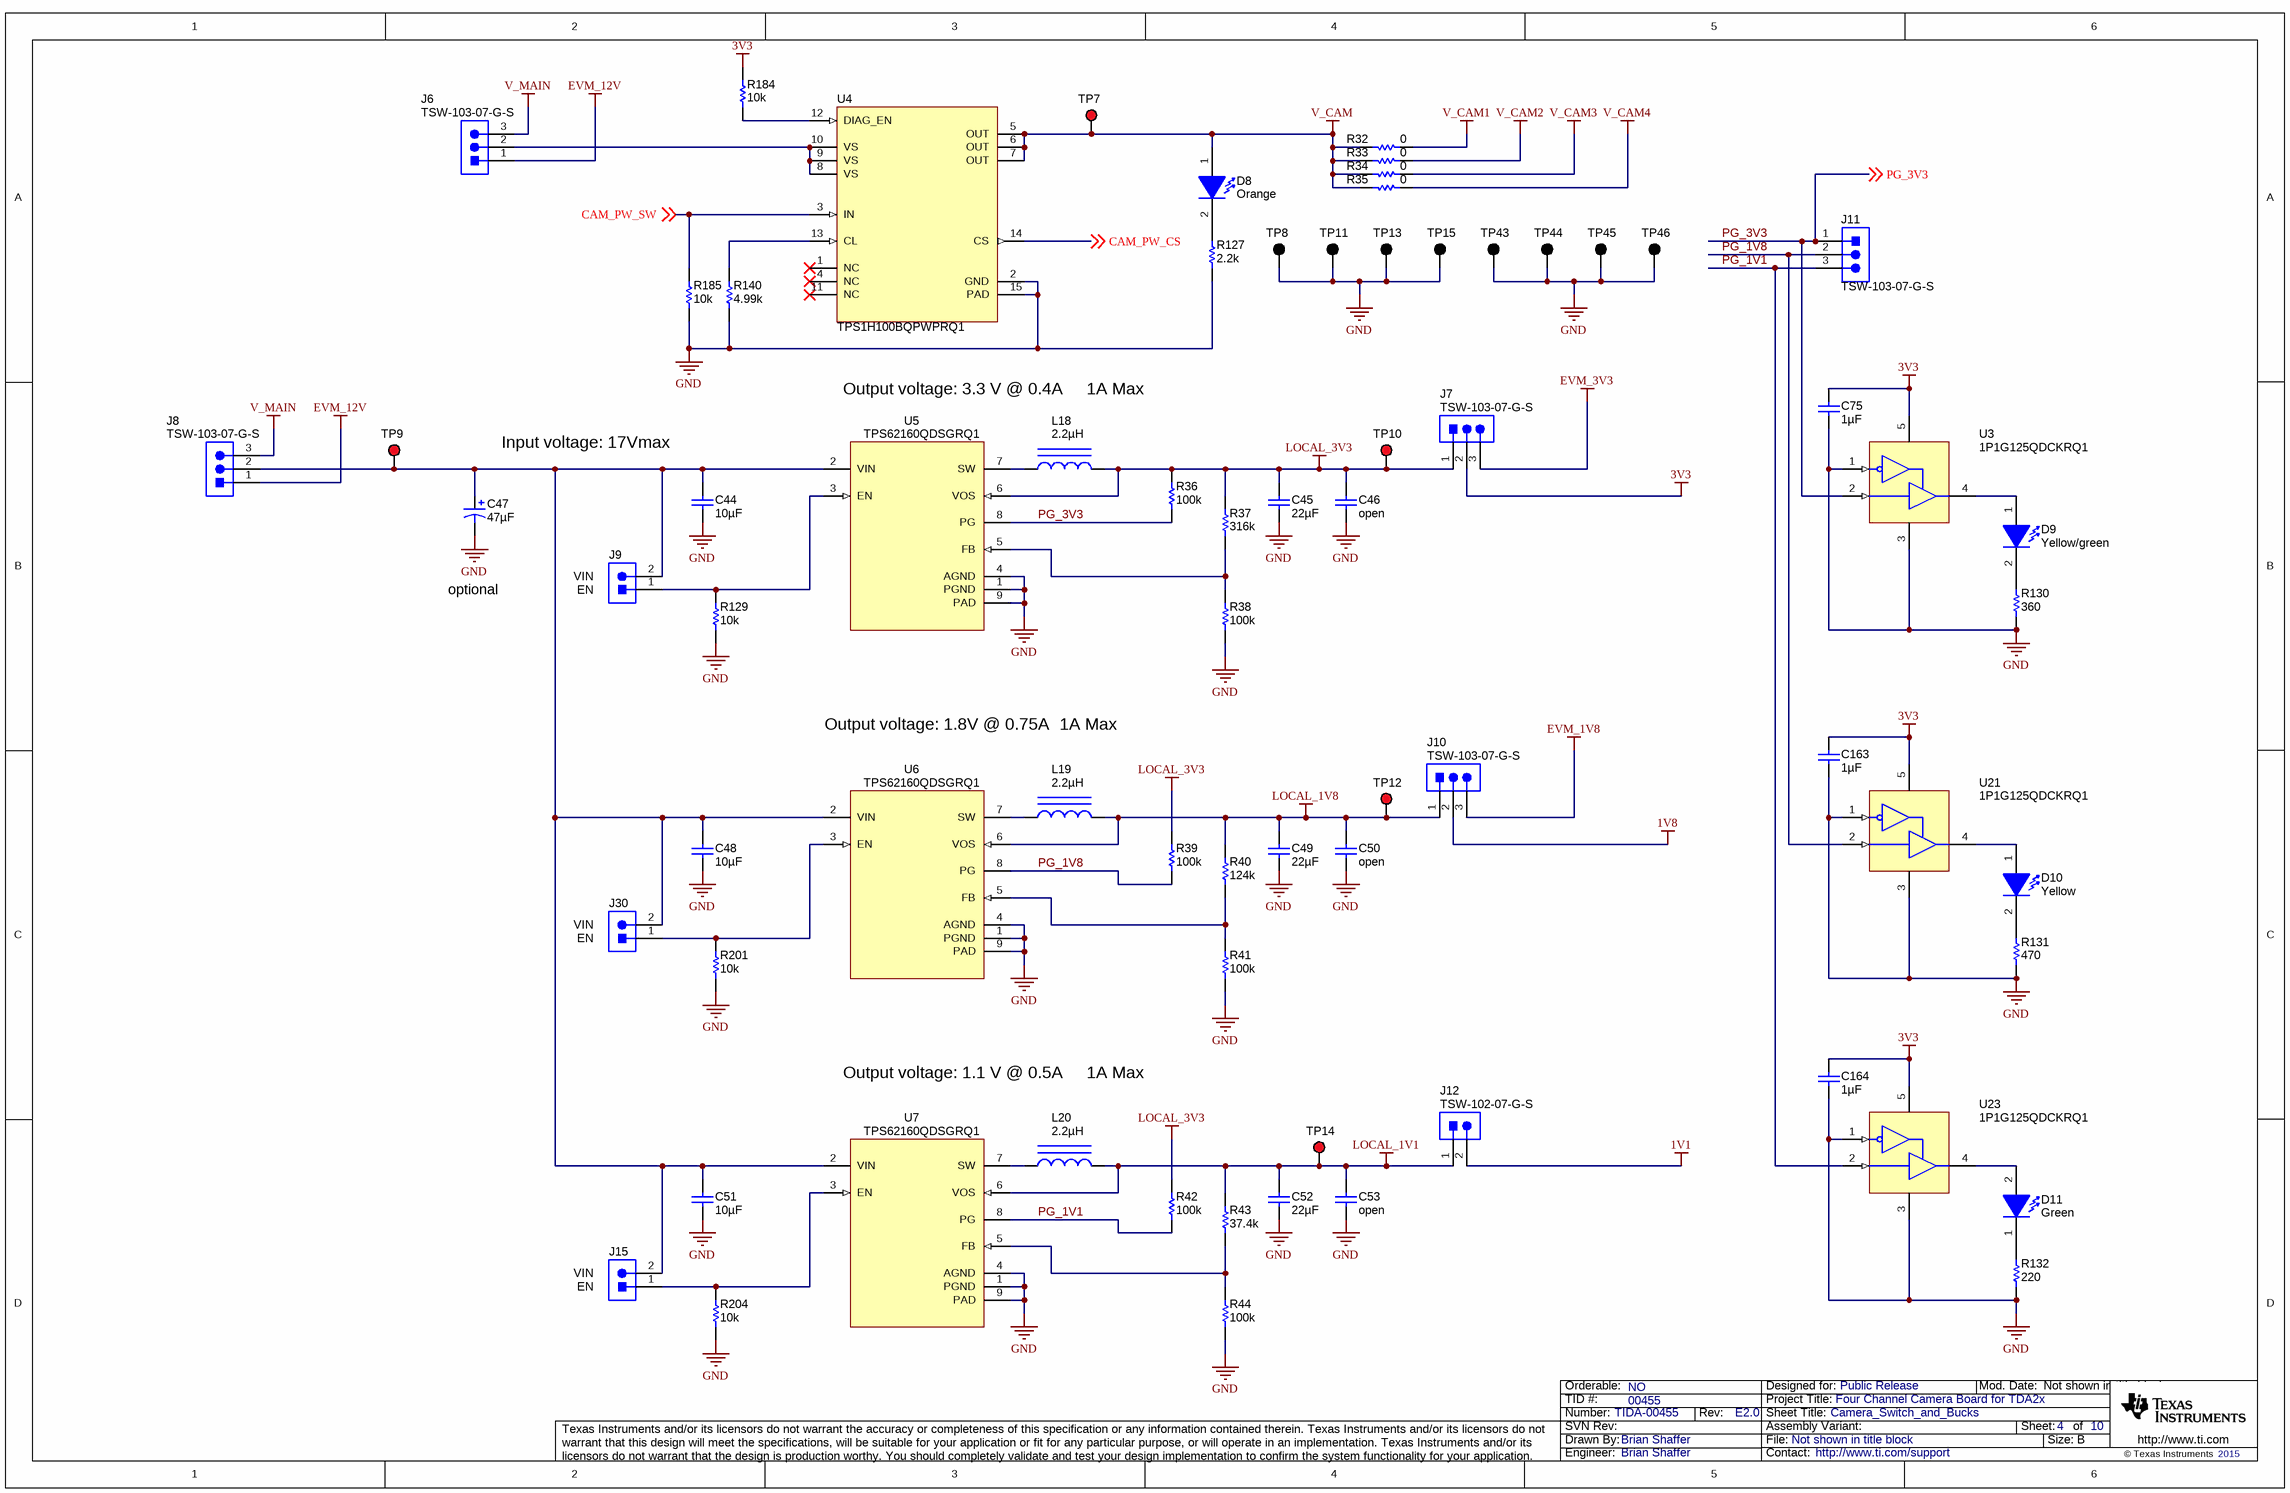
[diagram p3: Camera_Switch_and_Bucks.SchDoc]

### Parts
C44  ValueDisplayed: 10µF  [1206]  (hidden comment: GRM31CR71C106KAC7L)
C45  ValueDisplayed: 22µF  [1206]  (hidden comment: GRM31CR61C226KE15L)
C46  ValueDisplayed: open  [1206]
C47  ValueDisplayed: 47µF  [SM_RADIAL_D]  (hidden comment: EEE-FK1E470P)
C48  ValueDisplayed: 10µF  [1206]  (hidden comment: GRM31CR71C106KAC7L)
C49  ValueDisplayed: 22µF  [1206]  (hidden comment: GRM31CR61C226KE15L)
C50  ValueDisplayed: open  [1206]
C51  ValueDisplayed: 10µF  [1206]  (hidden comment: GRM31CR71C106KAC7L)
C52  ValueDisplayed: 22µF  [1206]  (hidden comment: GRM31CR61C226KE15L)
C53  ValueDisplayed: open  [1206]
C75  ValueDisplayed: 1µF  [0402]  (hidden comment: C1005JB1V105K050BC)
C163  ValueDisplayed: 1µF  [0402]  (hidden comment: C1005JB1V105K050BC)
C164  ValueDisplayed: 1µF  [0402]  (hidden comment: C1005JB1V105K050BC)
D8  value Orange  [LED_SMLP12_ORANGE]  (hidden comment: SML-P12DTT86)
D9  value Yellow/green  [SML-P1_YELLOW-GREEN]  (hidden comment: SML-P12MTT86)
D10  value Yellow  [LED_SMLP12_Yellow]  (hidden comment: SML-P12YTT86)
D11  value Green  [SML-P1_GREEN]  (hidden comment: SML-P12PTT86)
J6  TSW-103-07-G-S  [TSW-103-07-G-S]
J7  TSW-103-07-G-S  [TSW-103-07-G-S]
J8  TSW-103-07-G-S  [TSW-103-07-G-S]
J9  PEC02SAAN  [CONN_PEC02SAAN]  (value not drawn)
J10  TSW-103-07-G-S  [TSW-103-07-G-S]
J11  TSW-103-07-G-S  [TSW-103-07-G-S]
J12  TSW-102-07-G-S  [TSW-102-07-G-S]
J15  PEC02SAAN  [CONN_PEC02SAAN]  (value not drawn)
J30  PEC02SAAN  [CONN_PEC02SAAN]  (value not drawn)
L18  ValueDisplayed: 2.2µH  [VLS201610ET]  (hidden comment: VLS201610HBX-2R2M)
L19  ValueDisplayed: 2.2µH  [VLS201610ET]  (hidden comment: VLS201610HBX-2R2M)
L20  ValueDisplayed: 2.2µH  [VLS201610ET]  (hidden comment: VLS201610HBX-2R2M)
R32  value 0  [0603]  (hidden comment: CRCW06030000Z0EA)
R33  value 0  [0603]  (hidden comment: CRCW06030000Z0EA)
R34  value 0  [0603]  (hidden comment: CRCW06030000Z0EA)
R35  value 0  [0603]  (hidden comment: CRCW06030000Z0EA)
R36  ValueDisplayed: 100k  [0603]  (hidden comment: CRCW0603100KFKEA)
R37  ValueDisplayed: 316k  [0603]  (hidden comment: CRCW0603316KFKEA)
R38  ValueDisplayed: 100k  [0603]  (hidden comment: CRCW0603100KFKEA)
R39  ValueDisplayed: 100k  [0603]  (hidden comment: CRCW0603100KFKEA)
R40  ValueDisplayed: 124k  [0603]  (hidden comment: CRCW0603124KFKEA)
R41  ValueDisplayed: 100k  [0603]  (hidden comment: CRCW0603100KFKEA)
R42  ValueDisplayed: 100k  [0603]  (hidden comment: CRCW0603100KFKEA)
R43  ValueDisplayed: 37.4k  [0603]  (hidden comment: CRCW060337K4FKEA)
R44  ValueDisplayed: 100k  [0603]  (hidden comment: CRCW0603100KFKEA)
R127  ValueDisplayed: 2.2k  [0402]  (hidden comment: CRCW04022K20JNED)
R129  ValueDisplayed: 10k  [0402]  (hidden comment: CRCW040210K0JNED)
R130  ValueDisplayed: 360  [0402]  (hidden comment: CRCW0402360RJNED)
R131  ValueDisplayed: 470  [0402]  (hidden comment: CRCW0402470RJNED)
R132  ValueDisplayed: 220  [0402]  (hidden comment: CRCW0402220RJNED)
R140  ValueDisplayed: 4.99k  [0402]  (hidden comment: CRCW04024K99FKED)
R184  ValueDisplayed: 10k  [0402]  (hidden comment: CRCW040210K0JNED)
R185  ValueDisplayed: 10k  [0402]  (hidden comment: CRCW040210K0JNED)
R201  ValueDisplayed: 10k  [0402]  (hidden comment: CRCW040210K0JNED)
R204  ValueDisplayed: 10k  [0402]  (hidden comment: CRCW040210K0JNED)
TP7  5000  [Keystone5000]  (value not drawn)
TP8  5001  [Keystone5001]  (value not drawn)
TP9  5000  [Keystone5000]  (value not drawn)
TP10  5000  [Keystone5000]  (value not drawn)
TP11  5001  [Keystone5001]  (value not drawn)
TP12  5000  [Keystone5000]  (value not drawn)
TP13  5001  [Keystone5001]  (value not drawn)
TP14  5000  [Keystone5000]  (value not drawn)
TP15  5001  [Keystone5001]  (value not drawn)
TP43  5001  [Keystone5001]  (value not drawn)
TP44  5001  [Keystone5001]  (value not drawn)
TP45  5001  [Keystone5001]  (value not drawn)
TP46  5001  [Keystone5001]  (value not drawn)
U3  1P1G125QDCKRQ1  [DCK0005A_N]
U4  TPS1H100BQPWPRQ1  [PWP0014C_N]
U5  TPS62160QDSGRQ1  [DSG0008A]
U6  TPS62160QDSGRQ1  [DSG0008A]
U7  TPS62160QDSGRQ1  [DSG0008A]
U21  1P1G125QDCKRQ1  [DCK0005A_N]
U23  1P1G125QDCKRQ1  [DCK0005A_N]

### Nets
1V1: J12.2
1V8: J10.2
3V3: C75.1 C163.1 C164.1 J7.2 R184.2 U3.5(VCC) U21.5(VCC) U23.5(VCC)
EVM_1V8: J10.3
EVM_3V3: J7.3
EVM_12V: J6.1 J8.1
GND: C44.2 C45.2 C46.2 C47.2(-) C48.2 C49.2 C50.2 C51.2 C52.2 C53.2 C75.2 C163.2 C164.2 R38.1 R41.1 R44.1 R127.2 R129.1 R130.2 R131.1 R132.1 R140.1 R185.1 R201.1 R204.1 TP8.1 TP11.1 TP13.1 TP15.1 TP43.1 TP44.1 TP45.1 TP46.1 U3.1(~{OE}) U3.3(GND) U4.2(GND) U4.15(PAD) U5.1(PGND) U5.4(AGND) U5.9(PAD) U6.1(PGND) U6.4(AGND) U6.9(PAD) U7.1(PGND) U7.4(AGND) U7.9(PAD) U21.1(~{OE}) U21.3(GND) U23.1(~{OE}) U23.3(GND)
LOCAL_1V1: C52.1 C53.1 J12.1 L20.2 R43.2 TP14.1 U7.6(VOS)
LOCAL_1V8: C49.1 C50.1 J10.1 L19.2 R40.2 TP12.1 U6.6(VOS)
LOCAL_3V3: C45.1 C46.1 J7.1 L18.2 R36.2 R37.2 R39.1 R42.1 TP10.1 U5.6(VOS)
V_CAM: D8.1(A) R32.2 R33.2 R34.2 R35.2 TP7.1 U4.5(OUT) U4.6(OUT) U4.7(OUT)
V_CAM1: R32.1
V_CAM2: R33.1
V_CAM3: R34.1
V_CAM4: R35.1
V_MAIN: J6.3 J8.3
CAM_PW_CS: U4.14(CS) ; off-sheet CAM_PW_CS
CAM_PW_SW: R185.2 U4.3(IN) ; off-sheet CAM_PW_SW
PG_1V1: J11.3 R42.2 U7.8(PG) U23.2(A)
PG_1V8: J11.2 R39.2 U6.8(PG) U21.2(A)
PG_3V3: J11.1 R36.1 U3.2(A) U5.8(PG) ; off-sheet PG_3V3
NetC44_1: C44.1 C47.1(+) C48.1 C51.1 J8.2 J9.2 J15.2 J30.2 TP9.1 U5.2(VIN) U6.2(VIN) U7.2(VIN)
NetD8_2: D8.2(K) R127.1
NetD9_1: D9.1(A) U3.4(Y)
NetD9_2: D9.2(K) R130.1
NetD10_1: D10.1(A) U21.4(Y)
NetD10_2: D10.2(K) R131.2
NetD11_1: D11.1(K) R132.2
NetD11_2: D11.2(A) U23.4(Y)
NetJ6_2: J6.2 U4.8(VS) U4.9(VS) U4.10(VS)
NetJ9_1: J9.1 R129.2 U5.3(EN)
NetJ15_1: J15.1 R204.2 U7.3(EN)
NetJ30_1: J30.1 R201.2 U6.3(EN)
NetL18_1: L18.1 U5.7(SW)
NetL19_1: L19.1 U6.7(SW)
NetL20_1: L20.1 U7.7(SW)
NetR37_1: R37.1 R38.2 U5.5(FB)
NetR40_1: R40.1 R41.2 U6.5(FB)
NetR43_1: R43.1 R44.2 U7.5(FB)
NetR140_2: R140.2 U4.13(CL)
NetR184_1: R184.1 U4.12(DIAG_EN)

Not connected (* = marked no-connect by the designer): U4 1(NC)* 4(NC)* 11(NC)*

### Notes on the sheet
- Input voltage: 17Vmax
- Output voltage: 3.3 V @ 0.4A
- 1A Max
- (near J9) VIN
- optional
- (near J9) EN
- Output voltage: 1.8V @ 0.75A
- (near J30) EN
- (near J30) VIN
- Output voltage: 1.1 V @ 0.5A
- (near J15) EN
- (near J15) VIN

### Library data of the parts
C44 C48 C51 = GRM31CR71C106KAC7L: Cap, Cer-X7R, 10uF, 16V, 10%, 1206; Manufacturer: MuRata; Polarized: N; CompType: Capacitor; U/M: EA; Cap_F: 0.00001; Tolerance_%: 10; Value1: Unknown; VDC_V: 16; TempCo: X7R; TaMin_C: -55; TaMax_C: 125; EN: 102-1-01896; Mfg: MURATA MANUFACTURING CO,LTD; Onhand: 0
C45 C49 C52 = GRM31CR61C226KE15L: CAP, CERM, 22 µF, 16 V, +/- 10%, X5R, 1206; Manufacturer: MuRata; Polarized: N; CompType: Capacitor; Value: 22uF; U/M: EA; Cap_F: 0.000022; Tolerance_%: 10; Value1: Unknown; VDC_V: 16; Value2: 16V; TaMin_C: -55; TaMax_C: 85
C46 C50 C53 = GRM31CR61C226KE15L: CAP, open, 1206; Polarized: N; CompType: Capacitor; U/M: EA; Cap_F: 0.000022; Tolerance_%: 10; Value1: Unknown; TempCo: X5R; TaMin_C: -55; TaMax_C: 85
C47 = EEE-FK1E470P: CAP, AL, 47 µF, 25 V, +/- 20%, 0.36 ohm, SMD; Manufacturer: Panasonic; Polarized: Y; CompType: Capacitor; Value: 47uF; U/M: EA; Cap_F: 0.000047; Tolerance_%: 20; VDC_V: 25; Value2: 25V; ESR_ohm: 0.36; IRMS_A: 0.24; TaMin_C: -55; TaMax_C: 105; Cap_Case: D
C75 C163 C164 = C1005JB1V105K050BC: CAP, CERM, 1 µF, 35 V, +/- 10%, JB, 0402; Manufacturer: TDK; Polarized: N; CompType: Capacitor; Value: 1uF; U/M: EA; Cap_F: 0.000001; Tolerance_%: 10; Value1: Unknown; VDC_V: 35; Value2: 35V; TaMin_C: -25; TaMax_C: 85
D8 = SML-P12DTT86: LED, Orange, SMD; Manufacturer: Rohm; Type: InGaN; Vf_V: 2.1; Value2: 2.1V; Io_A: 0.02; Tjmax_C: 85; Value1: W; U/M: EA
D9 = SML-P12MTT86: LED, Yellow/green, SMD; Manufacturer: Rohm; Type: AlInGaP; Vf_V: 2.2; Value2: 2.2V; Io_A: 0.02; Value1: W; U/M: EA
D10 = SML-P12YTT86: LED, Yellow, SMD; Manufacturer: Rohm; Type: InGaN; Vf_V: 2.1; Value2: 2.1V; Io_A: 0.02; Tjmax_C: 85; Value1: W; U/M: EA
D11 = SML-P12PTT86: as D7 on sheet V_Batt_Supply
J6-J8 J10 J11 = TSW-103-07-G-S: Header, 100mil, 3x1, Gold, TH; Manufacturer: Samtec; SymbolCreator: a0799628; U/M: EA
J9 J15 J30 = PEC02SAAN: as J13 on sheet V_Batt_Supply
J12 = TSW-102-07-G-S: Header, 100mil, 2x1, Gold, TH; Manufacturer: Samtec; SymbolCreator: a0412235; U/M: EA
L18-L20 = VLS201610ET-2R2M: Inductor, Shielded, Ferrite, 2.2 µH, 1.45 A, 0.170 ohm, SMD; Manufacturer: TDK; Value: 2.2uH; Value2: 1.45A
R32-R35 = CRCW06030000Z0EA: RES, 0 ohm, 5%, 0.1W, 0603; Manufacturer: Vishay-Dale; CompType: Resistor; Value_Code: 0000; Tolerance_%: 5; Power_W: 0.1; VDC_V: 75; TempCo: 200 ppm/C; EIA_Code: E24; U/M: EA
R36 R38 R39 R41 R42 R44 = CRCW0603100KFKEA: RES, 100 k, 1%, 0.1 W, 0603; Manufacturer: Vishay-Dale; CompType: Resistor; Value: 100k; Res_ohm: 100000; Tolerance_%: 1; Power_W: 0.1; Value2: 0.1W; VDC_V: 75; TempCo: 100 ppm/C; EIA_Code: E96; U/M: EA
R37 = CRCW0603316KFKEA: RES, 316 k, 1%, 0.1 W, 0603; Manufacturer: Vishay-Dale; CompType: Resistor; Value: 316k; Res_ohm: 316000; Tolerance_%: 1; Power_W: 0.1; Value2: 0.1W; VDC_V: 75; TempCo: 100 ppm/C; EIA_Code: E96; U/M: EA
R40 = CRCW0603124KFKEA: RES, 124 k, 1%, 0.1 W, 0603; Manufacturer: Vishay-Dale; CompType: Resistor; Value: 124k; Res_ohm: 124000; Tolerance_%: 1; Power_W: 0.1; Value2: 0.1W; VDC_V: 75; TempCo: 100 ppm/C; EIA_Code: E96; U/M: EA
R43 = CRCW060337K4FKEA: RES, 37.4 k, 1%, 0.1 W, 0603; Manufacturer: Vishay-Dale; CompType: Resistor; Value: 37.4k; Res_ohm: 37400; Value_Code: 37k4; Tolerance_%: 1; Power_W: 0.1; Value2: 0.1W; VDC_V: 75; TempCo: 100 ppm/C; EIA_Code: E96; U/M: EA
R127 = CRCW04022K20JNED: as R50 on sheet V_Batt_Supply
R129 R184 R185 R201 R204 = CRCW040210K0JNED: RES, 10 k, 5%, 0.063 W, 0402; Manufacturer: Vishay-Dale; CompType: Resistor; Value: 10k; Res_ohm: 10000; Value_Code: 10k0; Tolerance_%: 5; Power_W: 0.063; Value2: 0.063W; VDC_V: 50; TempCo: 200 ppm/C; EIA_Code: E24; U/M: EA
R130 = CRCW0402360RJNED: RES, 360, 5%, 0.063 W, 0402; Manufacturer: Vishay-Dale; CompType: Resistor; Value: 360; Value_Code: 360R; Tolerance_%: 5; Power_W: 0.063; Value2: 0.063W; VDC_V: 50; TempCo: 200 ppm/C; EIA_Code: E24; U/M: EA
R131 = CRCW0402470RJNED: RES, 470, 5%, 0.063 W, 0402; Manufacturer: Vishay-Dale; CompType: Resistor; Value: 470; Value_Code: 470R; Tolerance_%: 5; Power_W: 0.063; Value2: 0.063W; VDC_V: 50; TempCo: 200 ppm/C; EIA_Code: E24; U/M: EA
R132 = CRCW0402220RJNED: RES, 220, 5%, 0.063 W, 0402; Manufacturer: Vishay-Dale; CompType: Resistor; Value: 220; Value_Code: 220R; Tolerance_%: 5; Power_W: 0.063; Value2: 0.063W; VDC_V: 50; TempCo: 200 ppm/C; EIA_Code: E24; U/M: EA
R140 = CRCW04024K99FKED: RES, 4.99 k, 1%, 0.063 W, 0402; Manufacturer: Vishay-Dale; CompType: Resistor; Value: 4.99k; Res_ohm: 4990; Value_Code: 4k99; Tolerance_%: 1; Power_W: 0.063; Value2: 0.063W; VDC_V: 50; TempCo: 100 ppm/C; EIA_Code: E96; U/M: EA
TP7 TP9 TP10 TP12 TP14 = 5000: as TP1 on sheet cam_connections
TP8 TP11 TP13 TP15 TP43-TP46 = 5001: Test Point, Miniature, Black, TH; Manufacturer: Keystone; CompType: Test Point Loop; U/M: EA
U3 U21 U23 = SN74LVC1G125DCKR: Single Bus Buffer Gate With 3-State Output, DCK0005A; Alternate PartNumber: SN74LVC1G125DCKT; Manufacturer: Texas Instruments; SymbolCreator: Altium; CompType: IC; U/M: EA
U4 = TPS1H100BQPWPRQ1: 40V/100mΩ Single Channel Smart High Side Switch, Automotive Qualified, PWP0014C; Manufacturer: Texas Instruments; SymbolCreator: a0411947; CompType: IC; U/M: EA
U5-U7 = TPS62160QDSGRQ1: 3-V to 17-V 1-A Step-Down Converter with DCS-Control™, DSG0008A; Alternate PartNumber: TPS62160QDSGTQ1; Manufacturer: Texas Instruments; SymbolCreator: Altium; CompType: IC; U/M: EA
